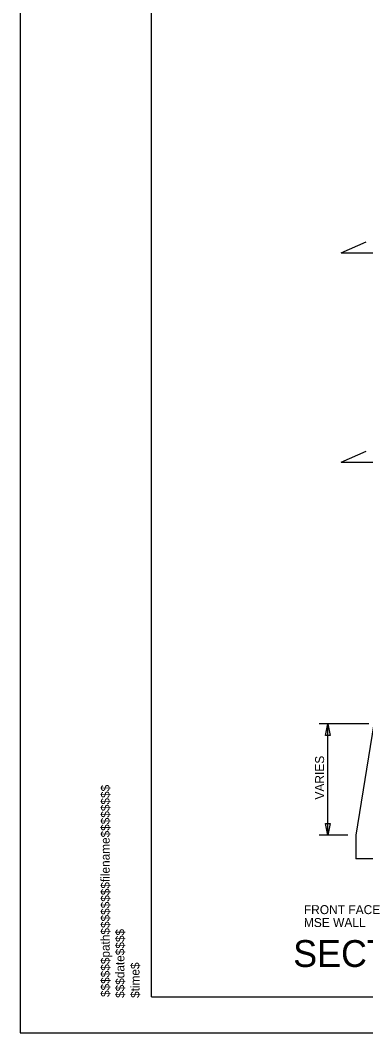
# Model space of a CAD drawing. Extents: x 96 to 240, y 601 to 689.
# Drawn here: x 95.8 to 115.2, y 601 to 657.6 of the extents above; entities that cross this region are included whole.
import ezdxf

# ---------------------------------------------------------------- set-up
doc = ezdxf.new("R2010")
doc.units = 0
for name, color, linetype in [('BR_AUTO DIMENSION', 7, 'Continuous'), ('BR_BORDER LINES', 7, 'Continuous'), ('BR_CONCRETE', 7, 'Continuous'), ('BR_TEXT', 7, 'Continuous'), ('Level 31', 7, 'Continuous'), ('RD_SHT_ID', 7, 'Continuous')]:
    doc.layers.add(name, color=color, linetype=linetype)

msp = doc.modelspace()

# ---------------------------------------------------------------- linework, layer by layer
at = {"layer": 'BR_AUTO DIMENSION'}
for p, q in [((113.78, 644.618), (115.181, 645.233)), ((113.78, 644.618), (116.921, 644.618)), ((113.78, 632.914), (115.181, 633.529)), ((113.78, 632.914), (116.921, 632.914)), ((115.328, 618.281), (112.555, 618.281)), ((113.036, 612.058), (113.036, 618.281)), ((114.157, 612.058), (112.555, 612.058))]:
    msp.add_line(p, q, dxfattribs=at)
for points in [[(112.911, 617.631), (113.036, 618.281), (113.161, 617.631)], [(113.161, 612.708), (113.036, 612.058), (112.911, 612.708)]]:
    msp.add_lwpolyline(points, close=True, dxfattribs=at)
at = {"layer": 'BR_BORDER LINES'}
for q in [(103.173, 687.003), (237.837, 603.003)]:
    msp.add_line((103.173, 603.003), q, dxfattribs=at)
at = {"layer": 'BR_CONCRETE'}
for p, q in [((115.608, 618.281), (114.608, 612.058)), ((114.608, 612.058), (114.608, 610.725)), ((117.274, 610.725), (114.608, 610.725))]:
    msp.add_line(p, q, dxfattribs=at)
at = {"layer": 'Level 31'}
msp.add_lwpolyline([(95.84, 601.004), (239.84, 601.004), (239.84, 689.004), (95.84, 689.004)], close=True, dxfattribs=at)

# ---------------------------------------------------------------- texts
at = {"layer": 'BR_AUTO DIMENSION'}
msp.add_text('VARIES', height=0.5, rotation=90, dxfattribs=at).set_placement((112.825, 614.042))
for s, p in [('FRONT FACE', (111.695, 607.637)), ('MSE WALL', (111.695, 606.916))]:
    msp.add_text(s, height=0.5, dxfattribs=at).set_placement(p)
at = {"layer": 'BR_TEXT'}
msp.add_text('SECTION A-A', height=1.5, dxfattribs=at).set_placement((111.098, 604.683))
at = {"layer": 'RD_SHT_ID'}
for s, height, p in [('$$$$$$path$$$$$$$$filename$$$$$$$$', 0.49387, (100.839, 603.003)), ('$$$date$$$$', 0.49387, (101.662, 602.951)), ('$time$', 0.4939, (102.507, 602.951))]:
    msp.add_text(s, height=height, rotation=90, dxfattribs=at).set_placement(p)

doc.saveas('drawing.dxf')
